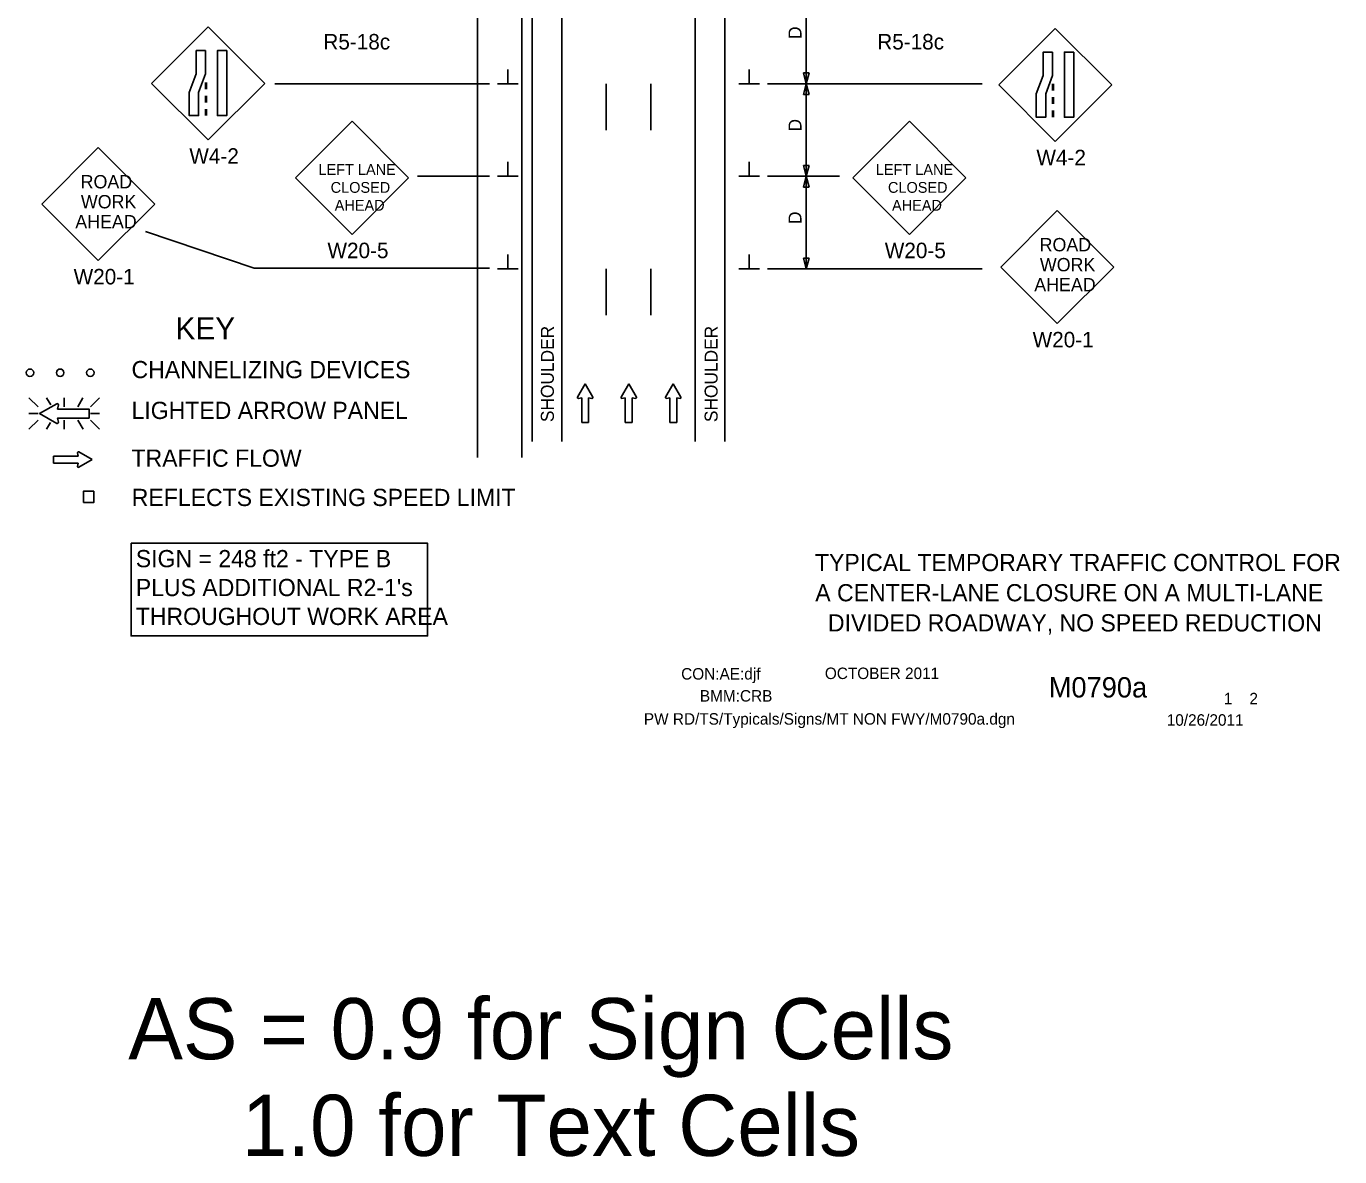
# Model space of a CAD drawing. Extents: x 16737 to 18482, y 6986 to 8195.
# Drawn here: x 16737 to 17446, y 6986 to 7597 of the extents above; entities that cross this region are included whole.
import ezdxf

# ---------------------------------------------------------------- set-up
doc = ezdxf.new("R2010")
doc.units = 0
for name, color, linetype in [('ALI_LEGAL_EX', 7, 'Continuous'), ('BORDER', 7, 'Continuous'), ('BORDER_SIGNAL_WO', 7, 'Continuous'), ('MT_SCRATCH_LEVEL_E', 7, 'Continuous'), ('PAVT_EDGE_EX', 7, 'Continuous'), ('TRAFFIC_SIGNS_PR', 7, 'Continuous'), ('TYPICAL_TEXT_DIMEN_EX', 7, 'Continuous'), ('TYPICAL_TEXT_DIMEN_PR', 7, 'Continuous')]:
    doc.layers.add(name, color=color, linetype=linetype)

msp = doc.modelspace()

# ---------------------------------------------------------------- linework, layer by layer
at = {"layer": 'ALI_LEGAL_EX'}
for p, q in [((16980.68, 8182.43), (16980.68, 7364.3)), ((17004.68, 8182.43), (17004.68, 7364.3))]:
    msp.add_line(p, q, dxfattribs=at)
for points in [[(17050.25, 7566.21), (17050.25, 7541.21)], [(17074.25, 7566.21), (17074.25, 7541.21)], [(17050.25, 7466.21), (17050.25, 7441.21)], [(17074.25, 7466.21), (17074.25, 7441.21)]]:
    msp.add_lwpolyline(points, dxfattribs=at)
at = {"layer": 'MT_SCRATCH_LEVEL_E'}
for p, q in [((17038.81, 7404.17), (17034.7, 7396.93)), ((17042.96, 7396.93), (17038.81, 7404.17)), ((17062.35, 7404.17), (17058.24, 7396.93)), ((17066.5, 7396.93), (17062.35, 7404.17)), ((17086.43, 7404.17), (17082.31, 7396.93)), ((17090.57, 7396.93), (17086.43, 7404.17)), ((17035.18, 7396.24), (17036.96, 7396.56)), ((17036.96, 7396.56), (17036.96, 7383.3)), ((17040.7, 7383.3), (17040.7, 7396.56)), ((17040.7, 7396.56), (17042.47, 7396.24)), ((17058.73, 7396.24), (17060.5, 7396.56)), ((17060.5, 7396.56), (17060.5, 7383.3)), ((17064.24, 7383.3), (17064.24, 7396.56)), ((17064.24, 7396.56), (17066.02, 7396.24)), ((17082.8, 7396.24), (17084.57, 7396.56)), ((17084.57, 7396.56), (17084.57, 7383.3)), ((17088.32, 7383.3), (17088.32, 7396.56)), ((17088.32, 7396.56), (17090.09, 7396.24)), ((17036.96, 7383.3), (17040.7, 7383.3)), ((17060.5, 7383.3), (17064.24, 7383.3)), ((17084.57, 7383.3), (17088.32, 7383.3)), ((16765.02, 7365.03), (16751.76, 7365.03)), ((16751.76, 7365.03), (16751.76, 7361.28)), ((16764.7, 7366.8), (16765.02, 7365.03)), ((16772.63, 7363.17), (16765.39, 7367.28)), ((16751.76, 7361.28), (16765.02, 7361.28)), ((16765.02, 7361.28), (16764.7, 7359.51)), ((16765.39, 7359.03), (16772.63, 7363.17))]:
    msp.add_line(p, q, dxfattribs=at)
for centre, start, end in [((17035.1, 7396.7), 150.42484, 279.96381), ((17042.55, 7396.7), 260.03619, 29.77312), ((17058.65, 7396.7), 150.42484, 279.96381), ((17066.09, 7396.7), 260.03619, 29.77312), ((17082.72, 7396.7), 150.42484, 279.96381), ((17090.16, 7396.7), 260.03619, 29.77312), ((16765.16, 7366.88), 60.42484, 189.96381), ((16765.16, 7359.44), 170.03619, 299.77312)]:
    msp.add_arc(centre, 0.463, start, end, dxfattribs=at)
at = {"layer": 'PAVT_EDGE_EX'}
for p, q in [((17010.25, 8166.21), (17010.25, 7372.95)), ((17026.25, 8166.21), (17026.25, 7372.95)), ((17098.25, 8166.21), (17098.25, 7372.95)), ((17114.25, 8166.21), (17114.25, 7372.95))]:
    msp.add_line(p, q, dxfattribs=at)
at = {"layer": 'TRAFFIC_SIGNS_PR'}
for p, q in [((16835.24, 7596.99), (16804.7, 7566.44)), ((16865.79, 7566.44), (16835.24, 7596.99)), ((17292.72, 7596.18), (17262.18, 7565.63)), ((17323.27, 7565.63), (17292.72, 7596.18)), ((16804.7, 7566.44), (16835.24, 7535.9)), ((16833.84, 7567), (16833.84, 7563.4)), ((16834.29, 7567), (16834.29, 7563.4)), ((16835.24, 7535.9), (16865.79, 7566.44)), ((17262.18, 7565.63), (17292.72, 7535.08)), ((17291.32, 7566.18), (17291.32, 7562.58)), ((17291.77, 7566.18), (17291.77, 7562.58)), ((17292.72, 7535.08), (17323.27, 7565.63)), ((16833.84, 7559.8), (16833.84, 7556.2)), ((16834.29, 7559.8), (16834.29, 7556.2)), ((17291.32, 7558.98), (17291.32, 7555.38)), ((17291.77, 7558.98), (17291.77, 7555.38)), ((16833.84, 7552.6), (16833.84, 7549)), ((16834.29, 7552.6), (16834.29, 7549)), ((17291.32, 7551.78), (17291.32, 7548.18)), ((17291.77, 7551.78), (17291.77, 7548.18)), ((16912.97, 7545.96), (16882.42, 7515.42)), ((16943.51, 7515.42), (16912.97, 7545.96)), ((17213.97, 7545.96), (17183.42, 7515.42)), ((17244.51, 7515.42), (17213.97, 7545.96)), ((16775.89, 7531.79), (16745.34, 7501.24)), ((16806.44, 7501.24), (16775.89, 7531.79)), ((16882.42, 7515.42), (16912.97, 7484.87)), ((16912.97, 7484.87), (16943.51, 7515.42)), ((17183.42, 7515.42), (17213.97, 7484.87)), ((17213.97, 7484.87), (17244.51, 7515.42)), ((16745.34, 7501.24), (16775.89, 7470.7)), ((16775.89, 7470.7), (16806.44, 7501.24)), ((17293.81, 7497.77), (17263.26, 7467.23)), ((17324.35, 7467.23), (17293.81, 7497.77)), ((17263.26, 7467.23), (17293.81, 7436.68)), ((17293.81, 7436.68), (17324.35, 7467.23)), ((16738.44, 7396.56), (16743.37, 7391.62)), ((16750.2, 7392.74), (16747.99, 7396.56)), ((16757.52, 7391.62), (16757.52, 7396.56)), ((16764.76, 7391.62), (16767.6, 7396.56)), ((16771.67, 7391.62), (16776.61, 7396.56)), ((16743.37, 7388.07), (16738.44, 7388.07)), ((16738.44, 7379.58), (16743.37, 7384.51)), ((16757.52, 7384.51), (16757.52, 7379.58)), ((16767.65, 7379.58), (16764.8, 7384.51)), ((16771.67, 7388.07), (16776.61, 7388.07)), ((16771.67, 7384.51), (16776.61, 7379.58)), ((16747.95, 7379.58), (16750.06, 7383.24))]:
    msp.add_line(p, q, dxfattribs=at)
for points in [[(16833.84, 7584.15), (16833.84, 7571.57), (16830.08, 7561.58), (16830.08, 7549), (16825.02, 7549), (16825.02, 7561.58), (16828.78, 7571.57), (16828.78, 7584.15)], [(16845.24, 7584.15), (16845.24, 7549), (16840.19, 7549), (16840.19, 7584.15)], [(17291.32, 7583.33), (17291.32, 7570.75), (17287.56, 7560.76), (17287.56, 7548.18), (17282.5, 7548.18), (17282.5, 7560.76), (17286.26, 7570.75), (17286.26, 7583.33)], [(17302.72, 7583.33), (17302.72, 7548.18), (17297.67, 7548.18), (17297.67, 7583.33)], [(16767.82, 7339.92), (16773.41, 7339.92), (16773.41, 7346.09), (16767.82, 7346.09)]]:
    msp.add_lwpolyline(points, close=True, dxfattribs=at)
for points in [[(16753.45, 7393.35), (16744.16, 7388.07), (16753.45, 7382.75)], [(16754.32, 7383.38), (16753.92, 7385.64), (16770.94, 7385.64), (16770.94, 7390.44), (16753.92, 7390.44), (16754.33, 7392.73)]]:
    msp.add_lwpolyline(points, dxfattribs=at)
for centre in [(16739, 7410.1), (16755.3, 7410.1), (16771.6, 7410.1)]:
    msp.add_circle(centre, 2, dxfattribs=at)
for centre, radius, start, end in [((16753.74, 7392.82), 0.598, 350.73078, 118.89165), ((16753.73, 7383.27), 0.597, 241.48329, 9.95933)]:
    msp.add_arc(centre, radius, start, end, dxfattribs=at)
at = {"layer": 'TYPICAL_TEXT_DIMEN_EX'}
msp.add_lwpolyline([(16793.57, 7317.98), (16953.74, 7317.98), (16953.74, 7267.86), (16793.57, 7267.86)], close=True, dxfattribs=at)
at = {"layer": 'TYPICAL_TEXT_DIMEN_PR'}
for p, q in [((17158.25, 7616.23), (17158.25, 7566.23)), ((16997.12, 7566.23), (16997.12, 7574.02)), ((17127.37, 7566.23), (17127.37, 7574.02)), ((17158.25, 7566.23), (17156.68, 7572.09)), ((17156.68, 7572.09), (17158.25, 7572.09)), ((17158.25, 7566.23), (17156.68, 7572.09)), ((17156.68, 7572.09), (17158.25, 7572.09)), ((17158.25, 7572.09), (17159.82, 7572.09)), ((17159.82, 7572.09), (17158.25, 7566.23)), ((17158.25, 7572.09), (17159.82, 7572.09)), ((17159.82, 7572.09), (17158.25, 7566.23)), ((16871.27, 7566.23), (16987.25, 7566.23)), ((16991.5, 7566.23), (17002.75, 7566.23)), ((17133, 7566.23), (17121.75, 7566.23)), ((17137.25, 7566.23), (17253.23, 7566.23)), ((17156.68, 7560.37), (17158.25, 7566.23)), ((17158.25, 7566.23), (17158.25, 7516.23)), ((17158.25, 7566.23), (17159.82, 7560.37)), ((17158.25, 7560.37), (17156.68, 7560.37)), ((17159.82, 7560.37), (17158.25, 7560.37)), ((16997.12, 7516.23), (16997.12, 7524.02)), ((17127.37, 7516.23), (17127.37, 7524.02)), ((17158.25, 7516.23), (17156.68, 7522.09)), ((17156.68, 7522.09), (17158.25, 7522.09)), ((17158.25, 7522.09), (17159.82, 7522.09)), ((17159.82, 7522.09), (17158.25, 7516.23)), ((16987.25, 7516.23), (16948.25, 7516.23)), ((16991.5, 7516.23), (17002.75, 7516.23)), ((17133, 7516.23), (17121.75, 7516.23)), ((17137.25, 7516.23), (17176.25, 7516.23)), ((17156.68, 7510.37), (17158.25, 7516.23)), ((17158.25, 7516.23), (17158.25, 7466.23)), ((17158.25, 7516.23), (17159.82, 7510.37)), ((17158.25, 7510.37), (17156.68, 7510.37)), ((17159.82, 7510.37), (17158.25, 7510.37)), ((16801.47, 7486.38), (16860.14, 7466.53)), ((16997.12, 7466.23), (16997.12, 7474.02)), ((17127.37, 7466.23), (17127.37, 7474.02)), ((17158.25, 7466.23), (17156.68, 7472.09)), ((17156.68, 7472.09), (17158.25, 7472.09)), ((17158.25, 7472.09), (17159.82, 7472.09)), ((17159.82, 7472.09), (17158.25, 7466.23)), ((16860.14, 7466.53), (16987.25, 7466.53)), ((16991.5, 7466.23), (17002.75, 7466.23)), ((17133, 7466.23), (17121.75, 7466.23)), ((17137.25, 7466.23), (17253.23, 7466.23))]:
    msp.add_line(p, q, dxfattribs=at)

# ---------------------------------------------------------------- texts
at = {"layer": 'BORDER'}
for s, p in [('TYPICAL TEMPORARY TRAFFIC CONTROL FOR', (17162.96, 7302.9)), ('A CENTER-LANE CLOSURE ON A MULTI-LANE', (17163.12, 7286.6)), ('DIVIDED ROADWAY, NO SPEED REDUCTION', (17169.96, 7270.3))]:
    msp.add_text(s, height=9.3, dxfattribs=at).set_placement(p)
at = {"layer": 'BORDER_SIGNAL_WO'}
for s, height, p in [('CON:AE:djf', 6.2, (17090.69, 7244.31)), ('    OCTOBER 2011    ', 6.2, (17159.08, 7244.59)), ('    M0790a   ', 11, (17272.86, 7234.63)), ('BMM:CRB   ', 6.2, (17100.81, 7232.42)), (' 1    2 ', 6.2, (17381.45, 7230.95)), ('PW RD/TS/Typicals/Signs/MT NON FWY/M0790a.dgn    ', 6.2, (17070.55, 7219.96)), ('10/26/2011    ', 6.2, (17352.93, 7219.38)), ('AS = 0.9 for Sign Cells', 33.0301, (16792.1, 7039.19)), ('     1.0 for Text Cells', 33.0301, (16792.1, 6986.96))]:
    msp.add_text(s, height=height, dxfattribs=at).set_placement(p)
at = {"layer": 'TRAFFIC_SIGNS_PR'}
for s, height, p in [('R5-18c', 8.37, (16897.45, 7584.76)), ('R5-18c', 8.37, (17196.6, 7584.76)), ('W4-2', 8.37, (16825.07, 7523.03)), ('W4-2', 8.37, (17282.55, 7522.21)), ('LEFT LANE', 5.85, (16894.83, 7516.99)), ('LEFT LANE', 5.85, (17195.83, 7516.99)), ('ROAD', 7.2, (16766.37, 7509.72)), ('CLOSED', 5.85, (16901.39, 7507.31)), ('CLOSED', 5.85, (17202.39, 7507.31)), ('WORK', 7.2, (16766.5, 7498.92)), ('AHEAD', 5.85, (16903.58, 7497.64)), ('AHEAD', 5.85, (17204.58, 7497.64)), ('AHEAD', 7.2, (16763.47, 7488.12)), ('W20-5', 8.37, (16899.66, 7472)), ('W20-5', 8.37, (17200.66, 7472)), ('ROAD', 7.2, (17284.29, 7475.7)), ('WORK', 7.2, (17284.42, 7464.9)), ('W20-1', 8.37, (16762.58, 7457.83)), ('AHEAD', 7.2, (17281.39, 7454.1)), ('W20-1', 8.37, (17280.5, 7423.81))]:
    msp.add_text(s, height=height, dxfattribs=at).set_placement(p)
at = {"layer": 'TYPICAL_TEXT_DIMEN_EX'}
for s, height, p in [('KEY', 12, (16817.66, 7428.06)), ('CHANNELIZING DEVICES', 9.3, (16793.84, 7407.16)), ('LIGHTED ARROW PANEL', 9.3, (16793.84, 7385.11)), ('TRAFFIC FLOW', 9.3, (16793.84, 7359.31)), ('REFLECTS EXISTING SPEED LIMIT', 9.3, (16793.98, 7338.08)), ('SIGN = 248 ft2 - TYPE B', 9.3, (16796.16, 7305.01)), ("PLUS ADDITIONAL R2-1's", 9.3, (16796.16, 7289.41)), ('THROUGHOUT WORK AREA', 9.3, (16796.16, 7273.81))]:
    msp.add_text(s, height=height, dxfattribs=at).set_placement(p)
at = {"layer": 'TYPICAL_TEXT_DIMEN_PR'}
for s, p in [('D', (17155.69, 7590.45)), ('D', (17155.69, 7540.45)), ('D', (17155.69, 7490.45)), ('SHOULDER', (17021.93, 7383.42)), ('SHOULDER', (17110.37, 7383.42))]:
    msp.add_text(s, height=7, rotation=90, dxfattribs=at).set_placement(p)

doc.saveas('drawing.dxf')
